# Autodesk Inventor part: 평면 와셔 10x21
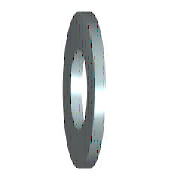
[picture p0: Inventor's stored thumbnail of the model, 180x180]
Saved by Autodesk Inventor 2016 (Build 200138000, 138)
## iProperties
IsCustomPart: 1
Created: 2012-02
Part Number: 평면 와셔 10x21
Material: 강철, 연강
Description: 평면 와셔
Document SubType Name: Modeling
Standard: KS B 1326
Designer: mduedu
Standards Organization: KS
Language: ko-KR
Size Designation: 10x21
Categories: <MemberInstance><Categories><Category DisplayName="조임쇠" InternalName="e4da775c-781d-43d5-af7c-5136215cf5a6" Mnemonic="FSTN"><Category DisplayName="와셔" InternalN
Density: 1 g/cm^3
Appearance: 노란색
Author: mduedu
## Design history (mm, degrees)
sketch "스케치"
  geometry: C1 r 10.5 at (0, 0); C2 r 5.25 at (0, 0); 1 further point
  constraints: 2 centre point, 2 coincident
  dimensions: "d0" = 10.5 diameter of C2 (= SD1); "d1" = 21 diameter of C1 (= SD2)
extrude "본체" new body sketch "스케치" distance "d2" = 2 (= SD); taper "d3" = 0 deg
workaxis "Work Axis1"
workplane "Work Plane1"
body "Solid1"
other parameters: "SD1" = 10.5 [user parameter; used in 1 equation term], "SD2" = 21 [user parameter; used in 1 equation term], "SD" = 2 [user parameter; used in 1 equation term], "d4" = 0, "d5" = 0, "d6" = 0, "d7" = 0
